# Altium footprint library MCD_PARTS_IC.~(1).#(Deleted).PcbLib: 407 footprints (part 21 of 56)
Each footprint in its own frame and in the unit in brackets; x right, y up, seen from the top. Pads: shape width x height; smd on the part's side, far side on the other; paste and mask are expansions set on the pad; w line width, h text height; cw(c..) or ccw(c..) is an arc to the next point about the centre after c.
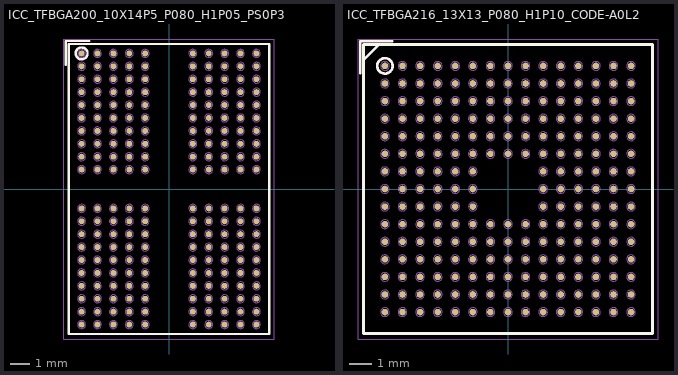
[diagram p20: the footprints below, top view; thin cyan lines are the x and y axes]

## ICC_TFBGA200_10X14P5_P080_H1P05_PS0P3 [mm]
height 1.05
pads (200):
  round 0.3 smd mask+0.05: A1(-4.4,6.825) A2(-3.6,6.825) A3(-2.8,6.825) A4(-2,6.825) A5(-1.2,6.825) A8(1.2,6.825) A9(2,6.825) A10(2.8,6.825) A11(3.6,6.825) A12(4.4,6.825) AA1(-4.4,-6.175) AA2(-3.6,-6.175) AA3(-2.8,-6.175) AA4(-2,-6.175) AA5(-1.2,-6.175) AA8(1.2,-6.175) AA9(2,-6.175) AA10(2.8,-6.175) AA11(3.6,-6.175) AA12(4.4,-6.175) AB1(-4.4,-6.825) AB2(-3.6,-6.825) AB3(-2.8,-6.825) AB4(-2,-6.825) AB5(-1.2,-6.825) AB8(1.2,-6.825) AB9(2,-6.825) AB10(2.8,-6.825) AB11(3.6,-6.825) AB12(4.4,-6.825) B1(-4.4,6.175) B2(-3.6,6.175) B3(-2.8,6.175) B4(-2,6.175) B5(-1.2,6.175) B8(1.2,6.175) B9(2,6.175) B10(2.8,6.175) B11(3.6,6.175) B12(4.4,6.175) C1(-4.4,5.525) C2(-3.6,5.525) C3(-2.8,5.525) C4(-2,5.525) C5(-1.2,5.525) C8(1.2,5.525) C9(2,5.525) C10(2.8,5.525) C11(3.6,5.525) C12(4.4,5.525) D1(-4.4,4.875) D2(-3.6,4.875) D3(-2.8,4.875) D4(-2,4.875) D5(-1.2,4.875) D8(1.2,4.875) D9(2,4.875) D10(2.8,4.875) D11(3.6,4.875) D12(4.4,4.875) E1(-4.4,4.225) E2(-3.6,4.225) E3(-2.8,4.225) E4(-2,4.225) E5(-1.2,4.225) E8(1.2,4.225) E9(2,4.225) E10(2.8,4.225) E11(3.6,4.225) E12(4.4,4.225) F1(-4.4,3.575) F2(-3.6,3.575) F3(-2.8,3.575) F4(-2,3.575) F5(-1.2,3.575) F8(1.2,3.575) F9(2,3.575) F10(2.8,3.575) F11(3.6,3.575) F12(4.4,3.575) G1(-4.4,2.925) G2(-3.6,2.925) G3(-2.8,2.925) G4(-2,2.925) G5(-1.2,2.925) G8(1.2,2.925) G9(2,2.925) G10(2.8,2.925) G11(3.6,2.925) G12(4.4,2.925) H1(-4.4,2.275) H2(-3.6,2.275) H3(-2.8,2.275) H4(-2,2.275) H5(-1.2,2.275) H8(1.2,2.275) H9(2,2.275) H10(2.8,2.275) H11(3.6,2.275) H12(4.4,2.275) J1(-4.4,1.625) J2(-3.6,1.625) J3(-2.8,1.625) J4(-2,1.625) J5(-1.2,1.625) J8(1.2,1.625) J9(2,1.625) J10(2.8,1.625) J11(3.6,1.625) J12(4.4,1.625) K1(-4.4,0.975) K2(-3.6,0.975) K3(-2.8,0.975) K4(-2,0.975) K5(-1.2,0.975) K8(1.2,0.975) K9(2,0.975) K10(2.8,0.975) K11(3.6,0.975) K12(4.4,0.975) N1(-4.4,-0.975) N2(-3.6,-0.975) N3(-2.8,-0.975) N4(-2,-0.975) N5(-1.2,-0.975) N8(1.2,-0.975) N9(2,-0.975) N10(2.8,-0.975) N11(3.6,-0.975) N12(4.4,-0.975) P1(-4.4,-1.625) P2(-3.6,-1.625) P3(-2.8,-1.625) P4(-2,-1.625) P5(-1.2,-1.625) P8(1.2,-1.625) P9(2,-1.625) P10(2.8,-1.625) P11(3.6,-1.625) P12(4.4,-1.625) R1(-4.4,-2.275) R2(-3.6,-2.275) R3(-2.8,-2.275) R4(-2,-2.275) R5(-1.2,-2.275) R8(1.2,-2.275) R9(2,-2.275) R10(2.8,-2.275) R11(3.6,-2.275) R12(4.4,-2.275) T1(-4.4,-2.925) T2(-3.6,-2.925) T3(-2.8,-2.925) T4(-2,-2.925) T5(-1.2,-2.925) T8(1.2,-2.925) T9(2,-2.925) T10(2.8,-2.925) T11(3.6,-2.925) T12(4.4,-2.925) U1(-4.4,-3.575) U2(-3.6,-3.575) U3(-2.8,-3.575) U4(-2,-3.575) U5(-1.2,-3.575) U8(1.2,-3.575) U9(2,-3.575) U10(2.8,-3.575) U11(3.6,-3.575) U12(4.4,-3.575) V1(-4.4,-4.225) V2(-3.6,-4.225) V3(-2.8,-4.225) V4(-2,-4.225) V5(-1.2,-4.225) V8(1.2,-4.225) V9(2,-4.225) V10(2.8,-4.225) V11(3.6,-4.225) V12(4.4,-4.225) W1(-4.4,-4.875) W2(-3.6,-4.875) W3(-2.8,-4.875) W4(-2,-4.875) W5(-1.2,-4.875) W8(1.2,-4.875) W9(2,-4.875) W10(2.8,-4.875) W11(3.6,-4.875) W12(4.4,-4.875) Y1(-4.4,-5.525) Y2(-3.6,-5.525) Y3(-2.8,-5.525) Y4(-2,-5.525) Y5(-1.2,-5.525) Y8(1.2,-5.525) Y9(2,-5.525) Y10(2.8,-5.525) Y11(3.6,-5.525) Y12(4.4,-5.525)
Top Overlay:
  circle w0.12: c-4.4,6.825 r0.3
  lines w0.12: -5.2,6.25 -5.2,7.45 -4,7.45 ; -5.05,-7.3 5.05,-7.3 5.05,7.3 -5.05,7.3 -5.05,-7.3
M14-Top Assembly:
  drawing of 204 lines, arcs and shapes, not listed
  text "A1" at -4.65,6.65 h0.4
  text "'.Designator'" at 0,0 h0.75
  text "A8" at 0.875,6.65 h0.4
  text "A12" at 3.925,6.65 h0.4
  text "K1" at -4.625,0.8 h0.4
  text "K5" at -1.5,0.8 h0.4
  text "K8" at 0.875,0.8 h0.4
  text "K12" at 3.95,0.8 h0.4
  text "N1" at -4.65,-1.15 h0.4
  text "N5" at -1.525,-1.15 h0.4
  text "N8" at 0.875,-1.15 h0.4
  text "N12" at 3.925,-1.15 h0.4
  text "AB1" at -4.825,-7 h0.4
  text "AB5" at -1.7,-7 h0.4
  text "AB8" at 0.7,-7 h0.4
  text "AB12" at 3.675,-7 h0.4
  text "A5" at -1.525,6.65 h0.4
M16-Top Courtyard:
  lines w0.01: -5.3,-7.55 -5.3,7.55 5.3,7.55 5.3,-7.55 -5.3,-7.55
3D body: height 1.06, standoff 1.05, extent -4.7,6.525 -4.1,7.125
3D body: height 0.36, standoff -0.04, extent 4.201,-2.472 4.6,-2.078
3D body: height 0.36, standoff -0.04, extent 3.401,-2.472 3.8,-2.078
3D body: height 0.36, standoff -0.04, extent 1.001,-2.472 1.4,-2.078
3D body: height 0.36, standoff -0.04, extent 1.801,-2.472 2.2,-2.078
3D body: height 0.36, standoff -0.04, extent 2.601,-2.472 3,-2.078
3D body: height 0.36, standoff -0.04, extent -4.599,-2.472 -4.2,-2.078
3D body: height 0.36, standoff -0.04, extent -3.799,-2.472 -3.4,-2.078
3D body: height 0.36, standoff -0.04, extent -2.999,-2.472 -2.6,-2.078
3D body: height 0.36, standoff -0.04, extent -2.199,-2.472 -1.8,-2.078
3D body: height 0.36, standoff -0.04, extent -1.399,-2.472 -1,-2.078
3D body: height 0.36, standoff -0.04, extent 4.201,-1.822 4.6,-1.428
3D body: height 0.36, standoff -0.04, extent 3.401,-1.822 3.8,-1.428
3D body: height 0.36, standoff -0.04, extent 1.001,-1.822 1.4,-1.428
3D body: height 0.36, standoff -0.04, extent 1.801,-1.822 2.2,-1.428
3D body: height 0.36, standoff -0.04, extent 2.601,-1.822 3,-1.428
3D body: height 0.36, standoff -0.04, extent -4.599,-1.822 -4.2,-1.428
3D body: height 0.36, standoff -0.04, extent -3.799,-1.822 -3.4,-1.428
3D body: height 0.36, standoff -0.04, extent -2.999,-1.822 -2.6,-1.428
3D body: height 0.36, standoff -0.04, extent -2.199,-1.822 -1.8,-1.428
3D body: height 0.36, standoff -0.04, extent -1.399,-1.822 -1,-1.428
3D body: height 0.36, standoff -0.04, extent 4.201,-1.172 4.6,-0.778
3D body: height 0.36, standoff -0.04, extent 3.401,-1.172 3.8,-0.778
3D body: height 0.36, standoff -0.04, extent 1.001,-1.172 1.4,-0.778
3D body: height 0.36, standoff -0.04, extent 1.801,-1.172 2.2,-0.778
3D body: height 0.36, standoff -0.04, extent 2.601,-1.172 3,-0.778
3D body: height 0.36, standoff -0.04, extent -4.599,-1.172 -4.2,-0.778
3D body: height 0.36, standoff -0.04, extent -3.799,-1.172 -3.4,-0.778
3D body: height 0.36, standoff -0.04, extent -2.999,-1.172 -2.6,-0.778
3D body: height 0.36, standoff -0.04, extent -2.199,-1.172 -1.8,-0.778
3D body: height 0.36, standoff -0.04, extent -1.399,-1.172 -1,-0.778
3D body: height 0.36, standoff -0.04, extent 3.401,0.778 3.8,1.172
3D body: height 0.36, standoff -0.04, extent 1.001,0.778 1.4,1.172
3D body: height 0.36, standoff -0.04, extent 1.801,0.778 2.2,1.172
3D body: height 0.36, standoff -0.04, extent 2.601,0.778 3,1.172
3D body: height 0.36, standoff -0.04, extent -4.599,0.778 -4.2,1.172
3D body: height 0.36, standoff -0.04, extent -3.799,0.778 -3.4,1.172
3D body: height 0.36, standoff -0.04, extent -2.999,0.778 -2.6,1.172
3D body: height 0.36, standoff -0.04, extent -2.199,0.778 -1.8,1.172
3D body: height 0.36, standoff -0.04, extent -1.399,0.778 -1,1.172
3D body: height 0.36, standoff -0.04, extent 3.401,1.428 3.8,1.822
3D body: height 0.36, standoff -0.04, extent 1.001,1.428 1.4,1.822
3D body: height 0.36, standoff -0.04, extent 1.801,1.428 2.2,1.822
3D body: height 0.36, standoff -0.04, extent 2.601,1.428 3,1.822
3D body: height 0.36, standoff -0.04, extent -4.599,1.428 -4.2,1.822
3D body: height 0.36, standoff -0.04, extent -3.799,1.428 -3.4,1.822
3D body: height 0.36, standoff -0.04, extent -2.999,1.428 -2.6,1.822
3D body: height 0.36, standoff -0.04, extent -2.199,1.428 -1.8,1.822
3D body: height 0.36, standoff -0.04, extent -1.399,1.428 -1,1.822
3D body: height 0.36, standoff -0.04, extent 3.401,2.078 3.8,2.472
3D body: height 0.36, standoff -0.04, extent 1.001,2.078 1.4,2.472
3D body: height 0.36, standoff -0.04, extent 1.801,2.078 2.2,2.472
3D body: height 0.36, standoff -0.04, extent 2.601,2.078 3,2.472
3D body: height 0.36, standoff -0.04, extent -4.599,2.078 -4.2,2.472
3D body: height 0.36, standoff -0.04, extent -3.799,2.078 -3.4,2.472
3D body: height 0.36, standoff -0.04, extent -2.999,2.078 -2.6,2.472
3D body: height 0.36, standoff -0.04, extent -2.199,2.078 -1.8,2.472
3D body: height 0.36, standoff -0.04, extent -1.399,2.078 -1,2.472
3D body: height 0.36, standoff -0.04, extent 3.401,2.728 3.8,3.122
3D body: height 0.36, standoff -0.04, extent 1.001,2.728 1.4,3.122
3D body: height 0.36, standoff -0.04, extent 1.801,2.728 2.2,3.122
3D body: height 0.36, standoff -0.04, extent 2.601,2.728 3,3.122
3D body: height 0.36, standoff -0.04, extent -4.599,2.728 -4.2,3.122
3D body: height 0.36, standoff -0.04, extent -3.799,2.728 -3.4,3.122
3D body: height 0.36, standoff -0.04, extent -2.999,2.728 -2.6,3.122
3D body: height 0.36, standoff -0.04, extent -2.199,2.728 -1.8,3.122
3D body: height 0.36, standoff -0.04, extent -1.399,2.728 -1,3.122
3D body: height 0.36, standoff -0.04, extent -4.599,3.378 -4.2,3.772
3D body: height 0.36, standoff -0.04, extent -3.799,3.378 -3.4,3.772
3D body: height 0.36, standoff -0.04, extent -2.999,3.378 -2.6,3.772
3D body: height 0.36, standoff -0.04, extent -2.199,3.378 -1.8,3.772
3D body: height 0.36, standoff -0.04, extent -1.399,3.378 -1,3.772
3D body: height 0.36, standoff -0.04, extent 4.201,4.028 4.6,4.422
3D body: height 0.36, standoff -0.04, extent 3.401,4.028 3.8,4.422
3D body: height 0.36, standoff -0.04, extent 1.001,4.028 1.4,4.422
3D body: height 0.36, standoff -0.04, extent 1.801,4.028 2.2,4.422
3D body: height 0.36, standoff -0.04, extent 2.601,4.028 3,4.422
3D body: height 0.36, standoff -0.04, extent -4.599,4.028 -4.2,4.422
3D body: height 0.36, standoff -0.04, extent -3.799,4.028 -3.4,4.422
3D body: height 0.36, standoff -0.04, extent -2.999,4.028 -2.6,4.422
3D body: height 0.36, standoff -0.04, extent -2.199,4.028 -1.8,4.422
3D body: height 0.36, standoff -0.04, extent -1.399,4.028 -1,4.422
3D body: height 0.36, standoff -0.04, extent 4.201,4.678 4.6,5.072
3D body: height 0.36, standoff -0.04, extent 3.401,4.678 3.8,5.072
3D body: height 0.36, standoff -0.04, extent 1.001,4.678 1.4,5.072
3D body: height 0.36, standoff -0.04, extent 1.801,4.678 2.2,5.072
3D body: height 0.36, standoff -0.04, extent 2.601,4.678 3,5.072
3D body: height 0.36, standoff -0.04, extent -4.599,4.678 -4.2,5.072
3D body: height 0.36, standoff -0.04, extent -3.799,4.678 -3.4,5.072
3D body: height 0.36, standoff -0.04, extent -2.999,4.678 -2.6,5.072
3D body: height 0.36, standoff -0.04, extent -2.199,4.678 -1.8,5.072
3D body: height 0.36, standoff -0.04, extent -1.399,4.678 -1,5.072
3D body: height 0.36, standoff -0.04, extent 4.201,5.328 4.6,5.722
3D body: height 0.36, standoff -0.04, extent 3.401,5.328 3.8,5.722
3D body: height 0.36, standoff -0.04, extent 1.001,5.328 1.4,5.722
3D body: height 0.36, standoff -0.04, extent 1.801,5.328 2.2,5.722
3D body: height 0.36, standoff -0.04, extent 2.601,5.328 3,5.722
3D body: height 0.36, standoff -0.04, extent -4.599,5.328 -4.2,5.722
3D body: height 0.36, standoff -0.04, extent -3.799,5.328 -3.4,5.722
3D body: height 0.36, standoff -0.04, extent -2.999,5.328 -2.6,5.722
3D body: height 0.36, standoff -0.04, extent -2.199,5.328 -1.8,5.722
3D body: height 0.36, standoff -0.04, extent -1.399,5.328 -1,5.722
3D body: height 0.36, standoff -0.04, extent 4.201,5.978 4.6,6.372
3D body: height 0.36, standoff -0.04, extent 3.401,5.978 3.8,6.372
3D body: height 0.36, standoff -0.04, extent 1.001,5.978 1.4,6.372
3D body: height 0.36, standoff -0.04, extent 1.801,5.978 2.2,6.372
3D body: height 0.36, standoff -0.04, extent 2.601,5.978 3,6.372
3D body: height 0.36, standoff -0.04, extent -4.599,5.978 -4.2,6.372
3D body: height 0.36, standoff -0.04, extent -3.799,5.978 -3.4,6.372
3D body: height 0.36, standoff -0.04, extent -2.999,5.978 -2.6,6.372
3D body: height 0.36, standoff -0.04, extent -2.199,5.978 -1.8,6.372
3D body: height 0.36, standoff -0.04, extent -1.399,5.978 -1,6.372
3D body: height 0.36, standoff -0.04, extent -1.399,6.628 -1,7.022
3D body: height 0.36, standoff -0.04, extent -2.199,6.628 -1.8,7.022
3D body: height 0.36, standoff -0.04, extent -2.999,6.628 -2.6,7.022
3D body: height 0.36, standoff -0.04, extent -3.799,6.628 -3.4,7.022
3D body: height 0.36, standoff -0.04, extent -4.599,6.628 -4.2,7.022
3D body: height 0.36, standoff -0.04, extent 2.601,6.628 3,7.022
3D body: height 0.36, standoff -0.04, extent 1.801,6.628 2.2,7.022
3D body: height 0.36, standoff -0.04, extent 1.001,6.628 1.4,7.022
3D body: height 0.36, standoff -0.04, extent 3.401,6.628 3.8,7.022
3D body: height 0.36, standoff -0.04, extent 4.201,6.628 4.6,7.022
3D body: height 1.05, standoff 0.3, extent -5.05,-7.3 5.05,7.3
3D body: height 0.36, standoff -0.04, extent -1.399,-3.122 -1,-2.728
3D body: height 0.36, standoff -0.04, extent -2.199,-3.122 -1.8,-2.728
3D body: height 0.36, standoff -0.04, extent -2.999,-3.122 -2.6,-2.728
3D body: height 0.36, standoff -0.04, extent -3.799,-3.122 -3.4,-2.728
3D body: height 0.36, standoff -0.04, extent -4.599,-3.122 -4.2,-2.728
3D body: height 0.36, standoff -0.04, extent 2.601,-3.122 3,-2.728
3D body: height 0.36, standoff -0.04, extent 1.801,-3.122 2.2,-2.728
3D body: height 0.36, standoff -0.04, extent 1.001,-3.122 1.4,-2.728
3D body: height 0.36, standoff -0.04, extent 3.401,-3.122 3.8,-2.728
3D body: height 0.36, standoff -0.04, extent 4.201,-3.122 4.6,-2.728
3D body: height 0.36, standoff -0.04, extent -1.399,-3.772 -1,-3.378
3D body: height 0.36, standoff -0.04, extent -2.199,-3.772 -1.8,-3.378
3D body: height 0.36, standoff -0.04, extent -2.999,-3.772 -2.6,-3.378
3D body: height 0.36, standoff -0.04, extent -3.799,-3.772 -3.4,-3.378
3D body: height 0.36, standoff -0.04, extent -4.599,-3.772 -4.2,-3.378
3D body: height 0.36, standoff -0.04, extent 2.601,-3.772 3,-3.378
3D body: height 0.36, standoff -0.04, extent 1.801,-3.772 2.2,-3.378
3D body: height 0.36, standoff -0.04, extent 1.001,-3.772 1.4,-3.378
3D body: height 0.36, standoff -0.04, extent 3.401,-3.772 3.8,-3.378
3D body: height 0.36, standoff -0.04, extent 4.201,-3.772 4.6,-3.378
3D body: height 0.36, standoff -0.04, extent 4.201,3.378 4.6,3.772
3D body: height 0.36, standoff -0.04, extent 3.401,3.378 3.8,3.772
3D body: height 0.36, standoff -0.04, extent 1.001,3.378 1.4,3.772
3D body: height 0.36, standoff -0.04, extent 1.801,3.378 2.2,3.772
3D body: height 0.36, standoff -0.04, extent 2.601,3.378 3,3.772
3D body: height 0.36, standoff -0.04, extent 4.201,0.778 4.6,1.172
3D body: height 0.36, standoff -0.04, extent 4.201,1.428 4.6,1.822
3D body: height 0.36, standoff -0.04, extent 4.201,2.078 4.6,2.472
3D body: height 0.36, standoff -0.04, extent 4.201,2.728 4.6,3.122
3D body: height 0.36, standoff -0.04, extent -1.399,-4.422 -1,-4.028
3D body: height 0.36, standoff -0.04, extent -2.199,-4.422 -1.8,-4.028
3D body: height 0.36, standoff -0.04, extent -2.999,-4.422 -2.6,-4.028
3D body: height 0.36, standoff -0.04, extent -3.799,-4.422 -3.4,-4.028
3D body: height 0.36, standoff -0.04, extent -4.599,-4.422 -4.2,-4.028
3D body: height 0.36, standoff -0.04, extent 2.601,-4.422 3,-4.028
3D body: height 0.36, standoff -0.04, extent 1.801,-4.422 2.2,-4.028
3D body: height 0.36, standoff -0.04, extent 1.001,-4.422 1.4,-4.028
3D body: height 0.36, standoff -0.04, extent 3.401,-4.422 3.8,-4.028
3D body: height 0.36, standoff -0.04, extent 4.201,-4.422 4.6,-4.028
3D body: height 0.36, standoff -0.04, extent -1.399,-5.072 -1,-4.678
3D body: height 0.36, standoff -0.04, extent -2.199,-5.072 -1.8,-4.678
3D body: height 0.36, standoff -0.04, extent -2.999,-5.072 -2.6,-4.678
3D body: height 0.36, standoff -0.04, extent -3.799,-5.072 -3.4,-4.678
3D body: height 0.36, standoff -0.04, extent -4.599,-5.072 -4.2,-4.678
3D body: height 0.36, standoff -0.04, extent 2.601,-5.072 3,-4.678
3D body: height 0.36, standoff -0.04, extent 1.801,-5.072 2.2,-4.678
3D body: height 0.36, standoff -0.04, extent 1.001,-5.072 1.4,-4.678
3D body: height 0.36, standoff -0.04, extent 3.401,-5.072 3.8,-4.678
3D body: height 0.36, standoff -0.04, extent 4.201,-5.072 4.6,-4.678
3D body: height 0.36, standoff -0.04, extent -1.399,-5.722 -1,-5.328
3D body: height 0.36, standoff -0.04, extent -2.199,-5.722 -1.8,-5.328
3D body: height 0.36, standoff -0.04, extent -2.999,-5.722 -2.6,-5.328
3D body: height 0.36, standoff -0.04, extent -3.799,-5.722 -3.4,-5.328
3D body: height 0.36, standoff -0.04, extent -4.599,-5.722 -4.2,-5.328
3D body: height 0.36, standoff -0.04, extent 2.601,-5.722 3,-5.328
3D body: height 0.36, standoff -0.04, extent 1.801,-5.722 2.2,-5.328
3D body: height 0.36, standoff -0.04, extent 1.001,-5.722 1.4,-5.328
3D body: height 0.36, standoff -0.04, extent 3.401,-5.722 3.8,-5.328
3D body: height 0.36, standoff -0.04, extent 4.201,-5.722 4.6,-5.328
3D body: height 0.36, standoff -0.04, extent -1.399,-6.372 -1,-5.978
3D body: height 0.36, standoff -0.04, extent -2.199,-6.372 -1.8,-5.978
3D body: height 0.36, standoff -0.04, extent -2.999,-6.372 -2.6,-5.978
3D body: height 0.36, standoff -0.04, extent -3.799,-6.372 -3.4,-5.978
3D body: height 0.36, standoff -0.04, extent -4.599,-6.372 -4.2,-5.978
3D body: height 0.36, standoff -0.04, extent 2.601,-6.372 3,-5.978
3D body: height 0.36, standoff -0.04, extent 1.801,-6.372 2.2,-5.978
3D body: height 0.36, standoff -0.04, extent 1.001,-6.372 1.4,-5.978
3D body: height 0.36, standoff -0.04, extent 3.401,-6.372 3.8,-5.978
3D body: height 0.36, standoff -0.04, extent 4.201,-6.372 4.6,-5.978
3D body: height 0.36, standoff -0.04, extent -1.399,-7.022 -1,-6.628
3D body: height 0.36, standoff -0.04, extent -2.199,-7.022 -1.8,-6.628
3D body: height 0.36, standoff -0.04, extent -2.999,-7.022 -2.6,-6.628
3D body: height 0.36, standoff -0.04, extent -3.799,-7.022 -3.4,-6.628
3D body: height 0.36, standoff -0.04, extent -4.599,-7.022 -4.2,-6.628
3D body: height 0.36, standoff -0.04, extent 2.601,-7.022 3,-6.628
3D body: height 0.36, standoff -0.04, extent 1.801,-7.022 2.2,-6.628
3D body: height 0.36, standoff -0.04, extent 1.001,-7.022 1.4,-6.628
3D body: height 0.36, standoff -0.04, extent 3.401,-7.022 3.8,-6.628
3D body: height 0.36, standoff -0.04, extent 4.201,-7.022 4.6,-6.628

## ICC_TFBGA216_13X13_P080_H1P10_CODE-A0L2 [mm] "MCD-02133"
height 1.1
pads (216):
  round 0.3 smd mask+0.05: A1(-5.6,5.6) A2(-4.8,5.6) A3(-4,5.6) A4(-3.2,5.6) A5(-2.4,5.6) A6(-1.6,5.6) A7(-0.8,5.6) A8(0,5.6) A9(0.8,5.6) A10(1.6,5.6) A11(2.4,5.6) A12(3.2,5.6) A13(4,5.6) A14(4.8,5.6) A15(5.6,5.6) B1(-5.6,4.8) B2(-4.8,4.8) B3(-4,4.8) B4(-3.2,4.8) B5(-2.4,4.8) B6(-1.6,4.8) B7(-0.8,4.8) B8(0,4.8) B9(0.8,4.8) B10(1.6,4.8) B11(2.4,4.8) B12(3.2,4.8) B13(4,4.8) B14(4.8,4.8) B15(5.6,4.8) C1(-5.6,4) C2(-4.8,4) C3(-4,4) C4(-3.2,4) C5(-2.4,4) C6(-1.6,4) C7(-0.8,4) C8(0,4) C9(0.8,4) C10(1.6,4) C11(2.4,4) C12(3.2,4) C13(4,4) C14(4.8,4) C15(5.6,4) D1(-5.6,3.2) D2(-4.8,3.2) D3(-4,3.2) D4(-3.2,3.2) D5(-2.4,3.2) D6(-1.6,3.2) D7(-0.8,3.2) D8(0,3.2) D9(0.8,3.2) D10(1.6,3.2) D11(2.4,3.2) D12(3.2,3.2) D13(4,3.2) D14(4.8,3.2) D15(5.6,3.2) E1(-5.6,2.4) E2(-4.8,2.4) E3(-4,2.4) E4(-3.2,2.4) E5(-2.4,2.4) E6(-1.6,2.4) E7(-0.8,2.4) E8(0,2.4) E9(0.8,2.4) E10(1.6,2.4) E11(2.4,2.4) E12(3.2,2.4) E13(4,2.4) E14(4.8,2.4) E15(5.6,2.4) F1(-5.6,1.6) F2(-4.8,1.6) F3(-4,1.6) F4(-3.2,1.6) F5(-2.4,1.6) F6(-1.6,1.6) F7(-0.8,1.6) F8(0,1.6) F9(0.8,1.6) F10(1.6,1.6) F11(2.4,1.6) F12(3.2,1.6) F13(4,1.6) F14(4.8,1.6) F15(5.6,1.6) G1(-5.6,0.8) G2(-4.8,0.8) G3(-4,0.8) G4(-3.2,0.8) G5(-2.4,0.8) G6(-1.6,0.8) G10(1.6,0.8) G11(2.4,0.8) G12(3.2,0.8) G13(4,0.8) G14(4.8,0.8) G15(5.6,0.8) H1(-5.6,0) H2(-4.8,0) H3(-4,0) H4(-3.2,0) H5(-2.4,0) H6(-1.6,0) H10(1.6,0) H11(2.4,0) H12(3.2,0) H13(4,0) H14(4.8,0) H15(5.6,0) J1(-5.6,-0.8) J2(-4.8,-0.8) J3(-4,-0.8) J4(-3.2,-0.8) J5(-2.4,-0.8) J6(-1.6,-0.8) J10(1.6,-0.8) J11(2.4,-0.8) J12(3.2,-0.8) J13(4,-0.8) J14(4.8,-0.8) J15(5.6,-0.8) K1(-5.6,-1.6) K2(-4.8,-1.6) K3(-4,-1.6) K4(-3.2,-1.6) K5(-2.4,-1.6) K6(-1.6,-1.6) K7(-0.8,-1.6) K8(0,-1.6) K9(0.8,-1.6) K10(1.6,-1.6) K11(2.4,-1.6) K12(3.2,-1.6) K13(4,-1.6) K14(4.8,-1.6) K15(5.6,-1.6) L1(-5.6,-2.4) L2(-4.8,-2.4) L3(-4,-2.4) L4(-3.2,-2.4) L5(-2.4,-2.4) L6(-1.6,-2.4) L7(-0.8,-2.4) L8(0,-2.4) L9(0.8,-2.4) L10(1.6,-2.4) L11(2.4,-2.4) L12(3.2,-2.4) L13(4,-2.4) L14(4.8,-2.4) L15(5.6,-2.4) M1(-5.6,-3.2) M2(-4.8,-3.2) M3(-4,-3.2) M4(-3.2,-3.2) M5(-2.4,-3.2) M6(-1.6,-3.2) M7(-0.8,-3.2) M8(0,-3.2) M9(0.8,-3.2) M10(1.6,-3.2) M11(2.4,-3.2) M12(3.2,-3.2) M13(4,-3.2) M14(4.8,-3.2) M15(5.6,-3.2) N1(-5.6,-4) N2(-4.8,-4) N3(-4,-4) N4(-3.2,-4) N5(-2.4,-4) N6(-1.6,-4) N7(-0.8,-4) N8(0,-4) N9(0.8,-4) N10(1.6,-4) N11(2.4,-4) N12(3.2,-4) N13(4,-4) N14(4.8,-4) N15(5.6,-4) P1(-5.6,-4.8) P2(-4.8,-4.8) P3(-4,-4.8) P4(-3.2,-4.8) P5(-2.4,-4.8) P6(-1.6,-4.8) P7(-0.8,-4.8) P8(0,-4.8) P9(0.8,-4.8) P10(1.6,-4.8) P11(2.4,-4.8) P12(3.2,-4.8) P13(4,-4.8) P14(4.8,-4.8) P15(5.6,-4.8) R1(-5.6,-5.6) R2(-4.8,-5.6) R3(-4,-5.6) R4(-3.2,-5.6) R5(-2.4,-5.6) R6(-1.6,-5.6) R7(-0.8,-5.6) R8(0,-5.6) R9(0.8,-5.6) R10(1.6,-5.6) R11(2.4,-5.6) R12(3.2,-5.6) R13(4,-5.6) R14(4.8,-5.6) R15(5.6,-5.6)
Top Overlay:
  circle w0.12: c-5.6,5.6 r0.35
  lines w0.12: -6.725,5.275 -6.725,6.725 -5.275,6.725 ; -6.55,5.895 -5.895,6.55 ; -6.575,-6.575 -6.575,6.575 6.575,6.575 6.575,-6.575 -6.575,-6.575
M14-Top Assembly:
  drawing of 220 lines, arcs and shapes, not listed
  text "A1" at -5.85,5.425 h0.4
  text "'.Designator'" at -2,-0.5 h0.75
M16-Top Courtyard:
  lines w0.01: -6.825,-6.825 -6.825,6.825 6.825,6.825 6.825,-6.825 -6.825,-6.825
3D body: height 1.11, standoff 1.1, extent -5.898,5.301 -5.3,5.9
3D body: height 0.36, standoff -0.04, extent 5.401,-5.797 5.8,-5.403
3D body: height 0.36, standoff -0.04, extent 4.601,-5.797 5,-5.403
3D body: height 0.36, standoff -0.04, extent 3.801,-5.797 4.2,-5.403
3D body: height 0.36, standoff -0.04, extent 3.001,-5.797 3.4,-5.403
3D body: height 0.36, standoff -0.04, extent 2.201,-5.797 2.6,-5.403
3D body: height 0.36, standoff -0.04, extent -1.799,-5.797 -1.4,-5.403
3D body: height 0.36, standoff -0.04, extent -0.999,-5.797 -0.6,-5.403
3D body: height 0.36, standoff -0.04, extent -0.199,-5.797 0.2,-5.403
3D body: height 0.36, standoff -0.04, extent 0.601,-5.797 1,-5.403
3D body: height 0.36, standoff -0.04, extent 1.401,-5.797 1.8,-5.403
3D body: height 0.36, standoff -0.04, extent -5.799,-5.797 -5.4,-5.403
3D body: height 0.36, standoff -0.04, extent -4.999,-5.797 -4.6,-5.403
3D body: height 0.36, standoff -0.04, extent -4.199,-5.797 -3.8,-5.403
3D body: height 0.36, standoff -0.04, extent -3.399,-5.797 -3,-5.403
3D body: height 0.36, standoff -0.04, extent -2.599,-5.797 -2.2,-5.403
3D body: height 0.36, standoff -0.04, extent 5.401,-4.997 5.8,-4.603
3D body: height 0.36, standoff -0.04, extent 4.601,-4.997 5,-4.603
3D body: height 0.36, standoff -0.04, extent 3.801,-4.997 4.2,-4.603
3D body: height 0.36, standoff -0.04, extent 3.001,-4.997 3.4,-4.603
3D body: height 0.36, standoff -0.04, extent 2.201,-4.997 2.6,-4.603
3D body: height 0.36, standoff -0.04, extent -1.799,-4.997 -1.4,-4.603
3D body: height 0.36, standoff -0.04, extent -0.999,-4.997 -0.6,-4.603
3D body: height 0.36, standoff -0.04, extent -0.199,-4.997 0.2,-4.603
3D body: height 0.36, standoff -0.04, extent 0.601,-4.997 1,-4.603
3D body: height 0.36, standoff -0.04, extent 1.401,-4.997 1.8,-4.603
3D body: height 0.36, standoff -0.04, extent -5.799,-4.997 -5.4,-4.603
3D body: height 0.36, standoff -0.04, extent -4.999,-4.997 -4.6,-4.603
3D body: height 0.36, standoff -0.04, extent -4.199,-4.997 -3.8,-4.603
3D body: height 0.36, standoff -0.04, extent -3.399,-4.997 -3,-4.603
3D body: height 0.36, standoff -0.04, extent -2.599,-4.997 -2.2,-4.603
3D body: height 0.36, standoff -0.04, extent 5.401,-4.197 5.8,-3.803
3D body: height 0.36, standoff -0.04, extent 4.601,-4.197 5,-3.803
3D body: height 0.36, standoff -0.04, extent 3.801,-4.197 4.2,-3.803
3D body: height 0.36, standoff -0.04, extent 3.001,-4.197 3.4,-3.803
3D body: height 0.36, standoff -0.04, extent 2.201,-4.197 2.6,-3.803
3D body: height 0.36, standoff -0.04, extent -1.799,-4.197 -1.4,-3.803
3D body: height 0.36, standoff -0.04, extent -0.999,-4.197 -0.6,-3.803
3D body: height 0.36, standoff -0.04, extent -0.199,-4.197 0.2,-3.803
3D body: height 0.36, standoff -0.04, extent 0.601,-4.197 1,-3.803
3D body: height 0.36, standoff -0.04, extent 1.401,-4.197 1.8,-3.803
3D body: height 0.36, standoff -0.04, extent -5.799,-4.197 -5.4,-3.803
3D body: height 0.36, standoff -0.04, extent -4.999,-4.197 -4.6,-3.803
3D body: height 0.36, standoff -0.04, extent -4.199,-4.197 -3.8,-3.803
3D body: height 0.36, standoff -0.04, extent -3.399,-4.197 -3,-3.803
3D body: height 0.36, standoff -0.04, extent -2.599,-4.197 -2.2,-3.803
3D body: height 0.36, standoff -0.04, extent 5.401,-3.397 5.8,-3.003
3D body: height 0.36, standoff -0.04, extent 4.601,-3.397 5,-3.003
3D body: height 0.36, standoff -0.04, extent 3.801,-3.397 4.2,-3.003
3D body: height 0.36, standoff -0.04, extent 3.001,-3.397 3.4,-3.003
3D body: height 0.36, standoff -0.04, extent 2.201,-3.397 2.6,-3.003
3D body: height 0.36, standoff -0.04, extent -1.799,-3.397 -1.4,-3.003
3D body: height 0.36, standoff -0.04, extent -0.999,-3.397 -0.6,-3.003
3D body: height 0.36, standoff -0.04, extent -0.199,-3.397 0.2,-3.003
3D body: height 0.36, standoff -0.04, extent 0.601,-3.397 1,-3.003
3D body: height 0.36, standoff -0.04, extent 1.401,-3.397 1.8,-3.003
3D body: height 0.36, standoff -0.04, extent -5.799,-3.397 -5.4,-3.003
3D body: height 0.36, standoff -0.04, extent -4.999,-3.397 -4.6,-3.003
3D body: height 0.36, standoff -0.04, extent -4.199,-3.397 -3.8,-3.003
3D body: height 0.36, standoff -0.04, extent -3.399,-3.397 -3,-3.003
3D body: height 0.36, standoff -0.04, extent -2.599,-3.397 -2.2,-3.003
3D body: height 0.36, standoff -0.04, extent 5.401,-2.597 5.8,-2.203
3D body: height 0.36, standoff -0.04, extent 4.601,-2.597 5,-2.203
3D body: height 0.36, standoff -0.04, extent 3.801,-2.597 4.2,-2.203
3D body: height 0.36, standoff -0.04, extent 3.001,-2.597 3.4,-2.203
3D body: height 0.36, standoff -0.04, extent 2.201,-2.597 2.6,-2.203
3D body: height 0.36, standoff -0.04, extent -1.799,-2.597 -1.4,-2.203
3D body: height 0.36, standoff -0.04, extent -0.999,-2.597 -0.6,-2.203
3D body: height 0.36, standoff -0.04, extent -0.199,-2.597 0.2,-2.203
3D body: height 0.36, standoff -0.04, extent 0.601,-2.597 1,-2.203
3D body: height 0.36, standoff -0.04, extent 1.401,-2.597 1.8,-2.203
3D body: height 0.36, standoff -0.04, extent -5.799,-2.597 -5.4,-2.203
3D body: height 0.36, standoff -0.04, extent -4.999,-2.597 -4.6,-2.203
3D body: height 0.36, standoff -0.04, extent -4.199,-2.597 -3.8,-2.203
3D body: height 0.36, standoff -0.04, extent -3.399,-2.597 -3,-2.203
3D body: height 0.36, standoff -0.04, extent -2.599,-2.597 -2.2,-2.203
3D body: height 0.36, standoff -0.04, extent 5.401,-1.797 5.8,-1.403
3D body: height 0.36, standoff -0.04, extent 4.601,-1.797 5,-1.403
3D body: height 0.36, standoff -0.04, extent 3.801,-1.797 4.2,-1.403
3D body: height 0.36, standoff -0.04, extent 3.001,-1.797 3.4,-1.403
3D body: height 0.36, standoff -0.04, extent 2.201,-1.797 2.6,-1.403
3D body: height 0.36, standoff -0.04, extent -1.799,-1.797 -1.4,-1.403
3D body: height 0.36, standoff -0.04, extent -0.999,-1.797 -0.6,-1.403
3D body: height 0.36, standoff -0.04, extent -0.199,-1.797 0.2,-1.403
3D body: height 0.36, standoff -0.04, extent 0.601,-1.797 1,-1.403
3D body: height 0.36, standoff -0.04, extent 1.401,-1.797 1.8,-1.403
3D body: height 0.36, standoff -0.04, extent -5.799,-1.797 -5.4,-1.403
3D body: height 0.36, standoff -0.04, extent -4.999,-1.797 -4.6,-1.403
3D body: height 0.36, standoff -0.04, extent -4.199,-1.797 -3.8,-1.403
3D body: height 0.36, standoff -0.04, extent -3.399,-1.797 -3,-1.403
3D body: height 0.36, standoff -0.04, extent -2.599,-1.797 -2.2,-1.403
3D body: height 0.36, standoff -0.04, extent 5.401,-0.997 5.8,-0.603
3D body: height 0.36, standoff -0.04, extent 4.601,-0.997 5,-0.603
3D body: height 0.36, standoff -0.04, extent 3.801,-0.997 4.2,-0.603
3D body: height 0.36, standoff -0.04, extent 3.001,-0.997 3.4,-0.603
3D body: height 0.36, standoff -0.04, extent 2.201,-0.997 2.6,-0.603
3D body: height 0.36, standoff -0.04, extent -1.799,-0.997 -1.4,-0.603
3D body: height 0.36, standoff -0.04, extent 1.401,-0.997 1.8,-0.603
3D body: height 0.36, standoff -0.04, extent -5.799,-0.997 -5.4,-0.603
3D body: height 0.36, standoff -0.04, extent -4.999,-0.997 -4.6,-0.603
3D body: height 0.36, standoff -0.04, extent -4.199,-0.997 -3.8,-0.603
3D body: height 0.36, standoff -0.04, extent -3.399,-0.997 -3,-0.603
3D body: height 0.36, standoff -0.04, extent -2.599,-0.997 -2.2,-0.603
3D body: height 0.36, standoff -0.04, extent 5.401,-0.197 5.8,0.197
3D body: height 0.36, standoff -0.04, extent 4.601,-0.197 5,0.197
3D body: height 0.36, standoff -0.04, extent 3.801,-0.197 4.2,0.197
3D body: height 0.36, standoff -0.04, extent 3.001,-0.197 3.4,0.197
3D body: height 0.36, standoff -0.04, extent 2.201,-0.197 2.6,0.197
3D body: height 0.36, standoff -0.04, extent -1.799,-0.197 -1.4,0.197
3D body: height 0.36, standoff -0.04, extent 1.401,-0.197 1.8,0.197
3D body: height 0.36, standoff -0.04, extent -5.799,-0.197 -5.4,0.197
3D body: height 0.36, standoff -0.04, extent -4.999,-0.197 -4.6,0.197
3D body: height 0.36, standoff -0.04, extent -4.199,-0.197 -3.8,0.197
3D body: height 0.36, standoff -0.04, extent -3.399,-0.197 -3,0.197
3D body: height 0.36, standoff -0.04, extent -2.599,-0.197 -2.2,0.197
3D body: height 0.36, standoff -0.04, extent 5.401,0.603 5.8,0.997
3D body: height 0.36, standoff -0.04, extent 4.601,0.603 5,0.997
3D body: height 0.36, standoff -0.04, extent 3.801,0.603 4.2,0.997
3D body: height 0.36, standoff -0.04, extent 3.001,0.603 3.4,0.997
3D body: height 0.36, standoff -0.04, extent 2.201,0.603 2.6,0.997
3D body: height 0.36, standoff -0.04, extent -1.799,0.603 -1.4,0.997
3D body: height 0.36, standoff -0.04, extent 1.401,0.603 1.8,0.997
3D body: height 0.36, standoff -0.04, extent -5.799,0.603 -5.4,0.997
3D body: height 0.36, standoff -0.04, extent -4.999,0.603 -4.6,0.997
3D body: height 0.36, standoff -0.04, extent -4.199,0.603 -3.8,0.997
3D body: height 0.36, standoff -0.04, extent -3.399,0.603 -3,0.997
3D body: height 0.36, standoff -0.04, extent -2.599,0.603 -2.2,0.997
3D body: height 0.36, standoff -0.04, extent 5.401,1.403 5.8,1.797
3D body: height 0.36, standoff -0.04, extent 4.601,1.403 5,1.797
3D body: height 0.36, standoff -0.04, extent 3.801,1.403 4.2,1.797
3D body: height 0.36, standoff -0.04, extent 3.001,1.403 3.4,1.797
3D body: height 0.36, standoff -0.04, extent 2.201,1.403 2.6,1.797
3D body: height 0.36, standoff -0.04, extent -1.799,1.403 -1.4,1.797
3D body: height 0.36, standoff -0.04, extent -0.999,1.403 -0.6,1.797
3D body: height 0.36, standoff -0.04, extent -0.199,1.403 0.2,1.797
3D body: height 0.36, standoff -0.04, extent 0.601,1.403 1,1.797
3D body: height 0.36, standoff -0.04, extent 1.401,1.403 1.8,1.797
3D body: height 0.36, standoff -0.04, extent -5.799,1.403 -5.4,1.797
3D body: height 0.36, standoff -0.04, extent -4.999,1.403 -4.6,1.797
3D body: height 0.36, standoff -0.04, extent -4.199,1.403 -3.8,1.797
3D body: height 0.36, standoff -0.04, extent -3.399,1.403 -3,1.797
3D body: height 0.36, standoff -0.04, extent -2.599,1.403 -2.2,1.797
3D body: height 0.36, standoff -0.04, extent 5.401,2.203 5.8,2.597
3D body: height 0.36, standoff -0.04, extent 4.601,2.203 5,2.597
3D body: height 0.36, standoff -0.04, extent 3.801,2.203 4.2,2.597
3D body: height 0.36, standoff -0.04, extent 3.001,2.203 3.4,2.597
3D body: height 0.36, standoff -0.04, extent 2.201,2.203 2.6,2.597
3D body: height 0.36, standoff -0.04, extent -1.799,2.203 -1.4,2.597
3D body: height 0.36, standoff -0.04, extent -0.999,2.203 -0.6,2.597
3D body: height 0.36, standoff -0.04, extent -0.199,2.203 0.2,2.597
3D body: height 0.36, standoff -0.04, extent 0.601,2.203 1,2.597
3D body: height 0.36, standoff -0.04, extent 1.401,2.203 1.8,2.597
3D body: height 0.36, standoff -0.04, extent -5.799,2.203 -5.4,2.597
3D body: height 0.36, standoff -0.04, extent -4.999,2.203 -4.6,2.597
3D body: height 0.36, standoff -0.04, extent -4.199,2.203 -3.8,2.597
3D body: height 0.36, standoff -0.04, extent -3.399,2.203 -3,2.597
3D body: height 0.36, standoff -0.04, extent -2.599,2.203 -2.2,2.597
3D body: height 0.36, standoff -0.04, extent 5.401,3.003 5.8,3.397
3D body: height 0.36, standoff -0.04, extent 4.601,3.003 5,3.397
3D body: height 0.36, standoff -0.04, extent 3.801,3.003 4.2,3.397
3D body: height 0.36, standoff -0.04, extent 3.001,3.003 3.4,3.397
3D body: height 0.36, standoff -0.04, extent 2.201,3.003 2.6,3.397
3D body: height 0.36, standoff -0.04, extent -1.799,3.003 -1.4,3.397
3D body: height 0.36, standoff -0.04, extent -0.999,3.003 -0.6,3.397
3D body: height 0.36, standoff -0.04, extent -0.199,3.003 0.2,3.397
3D body: height 0.36, standoff -0.04, extent 0.601,3.003 1,3.397
3D body: height 0.36, standoff -0.04, extent 1.401,3.003 1.8,3.397
3D body: height 0.36, standoff -0.04, extent -5.799,3.003 -5.4,3.397
3D body: height 0.36, standoff -0.04, extent -4.999,3.003 -4.6,3.397
3D body: height 0.36, standoff -0.04, extent -4.199,3.003 -3.8,3.397
3D body: height 0.36, standoff -0.04, extent -3.399,3.003 -3,3.397
3D body: height 0.36, standoff -0.04, extent -2.599,3.003 -2.2,3.397
3D body: height 0.36, standoff -0.04, extent 5.401,3.803 5.8,4.197
3D body: height 0.36, standoff -0.04, extent 4.601,3.803 5,4.197
3D body: height 0.36, standoff -0.04, extent 3.801,3.803 4.2,4.197
3D body: height 0.36, standoff -0.04, extent 3.001,3.803 3.4,4.197
3D body: height 0.36, standoff -0.04, extent 2.201,3.803 2.6,4.197
3D body: height 0.36, standoff -0.04, extent -1.799,3.803 -1.4,4.197
3D body: height 0.36, standoff -0.04, extent -0.999,3.803 -0.6,4.197
3D body: height 0.36, standoff -0.04, extent -0.199,3.803 0.2,4.197
3D body: height 0.36, standoff -0.04, extent 0.601,3.803 1,4.197
3D body: height 0.36, standoff -0.04, extent 1.401,3.803 1.8,4.197
3D body: height 0.36, standoff -0.04, extent -5.799,3.803 -5.4,4.197
3D body: height 0.36, standoff -0.04, extent -4.999,3.803 -4.6,4.197
3D body: height 0.36, standoff -0.04, extent -4.199,3.803 -3.8,4.197
3D body: height 0.36, standoff -0.04, extent -3.399,3.803 -3,4.197
3D body: height 0.36, standoff -0.04, extent -2.599,3.803 -2.2,4.197
3D body: height 0.36, standoff -0.04, extent 5.401,4.603 5.8,4.997
3D body: height 0.36, standoff -0.04, extent 4.601,4.603 5,4.997
3D body: height 0.36, standoff -0.04, extent 3.801,4.603 4.2,4.997
3D body: height 0.36, standoff -0.04, extent 3.001,4.603 3.4,4.997
3D body: height 0.36, standoff -0.04, extent 2.201,4.603 2.6,4.997
3D body: height 0.36, standoff -0.04, extent -1.799,4.603 -1.4,4.997
3D body: height 0.36, standoff -0.04, extent -0.999,4.603 -0.6,4.997
3D body: height 0.36, standoff -0.04, extent -0.199,4.603 0.2,4.997
3D body: height 0.36, standoff -0.04, extent 0.601,4.603 1,4.997
3D body: height 0.36, standoff -0.04, extent 1.401,4.603 1.8,4.997
3D body: height 0.36, standoff -0.04, extent -5.799,4.603 -5.4,4.997
3D body: height 0.36, standoff -0.04, extent -4.999,4.603 -4.6,4.997
3D body: height 0.36, standoff -0.04, extent -4.199,4.603 -3.8,4.997
3D body: height 0.36, standoff -0.04, extent -3.399,4.603 -3,4.997
3D body: height 0.36, standoff -0.04, extent -2.599,4.603 -2.2,4.997
3D body: height 0.36, standoff -0.04, extent -2.599,5.403 -2.2,5.797
3D body: height 0.36, standoff -0.04, extent -3.399,5.403 -3,5.797
3D body: height 0.36, standoff -0.04, extent -4.199,5.403 -3.8,5.797
3D body: height 0.36, standoff -0.04, extent -4.999,5.403 -4.6,5.797
3D body: height 0.36, standoff -0.04, extent -5.799,5.403 -5.4,5.797
3D body: height 0.36, standoff -0.04, extent 1.401,5.403 1.8,5.797
3D body: height 0.36, standoff -0.04, extent 0.601,5.403 1,5.797
3D body: height 0.36, standoff -0.04, extent -0.199,5.403 0.2,5.797
3D body: height 0.36, standoff -0.04, extent -0.999,5.403 -0.6,5.797
3D body: height 0.36, standoff -0.04, extent -1.799,5.403 -1.4,5.797
3D body: height 0.36, standoff -0.04, extent 2.201,5.403 2.6,5.797
3D body: height 0.36, standoff -0.04, extent 3.001,5.403 3.4,5.797
3D body: height 0.36, standoff -0.04, extent 3.801,5.403 4.2,5.797
3D body: height 0.36, standoff -0.04, extent 4.601,5.403 5,5.797
3D body: height 1.1, standoff 0.3, extent -6.55,-6.55 6.55,6.55
3D body: height 0.36, standoff -0.04, extent 5.401,5.403 5.8,5.797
